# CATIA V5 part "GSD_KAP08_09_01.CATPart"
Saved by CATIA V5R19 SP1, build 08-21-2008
Part number: GSD_ANALYSIS_05
Description: Beispielmodell: Eltern / Kinder, Ereignisprotokollgrafik  Maik Hertha IT Consultants
Publications: "Ausgangsflaeche"
Bounding box of the stored display mesh (mm): x 45.005 to 391.048, y -251.452 to 318.537, z 79.732 to 163.217
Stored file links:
  \GSD_BUCH_UEBUNG\GSD_KAP08_09_01.CATPart
  C:\Program Files\Dassault Systemes\B19\win_b64\startup\materials\Catalog.CATMaterial
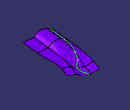
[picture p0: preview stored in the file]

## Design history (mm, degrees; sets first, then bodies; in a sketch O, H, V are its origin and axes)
AxisSystem1 "Absolute Axis System": origin (0, 0, 0), X (1, 0, 0), Y (0, 1, 0), Z (0, 0, 1)
Set1
  Sketch1 on XY plane of AxisSystem1, origin (0, 0, 0), H (1, 0, 0), V (0, 1, 0)
    spline S1 through (56.4923, -100.7832) (88.7426, 61.2206) (149.0894, 199.066)
  Sketch2 on YZ plane of AxisSystem1, origin (0, 0, 0), H (0, 1, 0), V (0, 0, 1)
    spline S1 through (-99.4141, 130.7483) (48.3525, 138.1953) (199.5081, 170.3531)
  Combine1: Curve1 Sketch2, Curve2 Sketch1
Set2
  Set3
    Plane1: type Normal, Curve Combine1, RefPoint {point type OnCurve, Support Combine1, Ratio 0}
    Sketch3 on Plane1, origin (149.0894, 199.066, 170.2213), H (0.8711, -0.4912, 0), V (-0.1233, -0.2188, 0.968)
      point P1 (0, -41.2234)
      line L1 (0, -41.2234) -> (55.1042, -60.3398)
      arc A1 centre (87.2142, 32.2196) radius 97.9708 from (55.1042, -60.3398) to (140.0568, -50.2785) ccw
      line L2 (140.0568, -50.2785) -> (199.1543, -50.2785)
      axis line L3 (0, -25.1255) -> (0, -95.554)
      point P6 (0, -25.1255)
      coincidence: P1 V, P6 V, P1 L3
      tangency: A1 L1
      horizontal: L2 H
      vertical: L3 V
    Extrude1: Lim1 131, Lim2 0, Element1 Sketch3, Direction Plane1
  Set4
    Plane2: type Normal, Curve Combine1, RefPoint {point type OnCurve, Support Combine1, Ratio 1}
    Sketch4 on Plane2, origin (56.6116, -99.4141, 130.7483), H (0.9961, -0.0877, 0), V (0.0023, 0.0264, 0.9996)
      point P1 (0, -50.7831)
      line L1 (0, -50.7831) -> (48.6659, -18.7973)
      arc A1 centre (92.7068, -85.8047) radius 80.1848 from (48.6659, -18.7973) to (154.6959, -34.9426) cw
      line L2 (154.6959, -34.9426) -> (235.5792, -34.9426)
      axis line L3 (0, -29.7328) -> (0, -112.44)
      point P6 (0, -29.7328)
      tangency: A1 L1
      horizontal: L2 H
      coincidence: P6 V, P1 L3
      vertical: L3 V
    Extrude2: Lim1 131, Lim2 0, Element1 Sketch4, Direction Plane2
  Loft1: Spine Combine1, Sections (Sketch4; Sketch3), EndSectionTangent Extrude1, StartSectionTangent Extrude2
Set5
  Plane3: type Equation, A 0, B 0, C 1, RefAxis AxisSystem1, Length 100
  Sketch5 on Plane3, origin (0, 0, 100), H (1, 0, 0), V (0, 1, 0)
    spline S1 through (82.6122, -259.0649) (82.6122, -123.4884) (176.2178, 97.2579)
    spline S2 through (257.6893, 338.8622) (269.8234, 218.9292) (176.2178, 97.2579)
    point P1 (176.2178, 97.2579)
    point P2 (176.2178, 97.2579)
    coincidence: P1 P2
  Join1: Elements (Extrude1; Loft1; Extrude2)
  Project1: Support Join1, ToProject Sketch5
Body1 (main body)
